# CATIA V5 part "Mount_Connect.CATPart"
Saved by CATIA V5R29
Part number: Mount_Connect
Source: Unknown
Bounding box of the stored display mesh (mm): x -80 to 35, y -25 to 25, z -45 to 45
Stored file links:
  C:\Users\Administrator\Desktop\프로젝트\Boxfold\Guide\Mount_Connect.CATPart
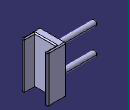
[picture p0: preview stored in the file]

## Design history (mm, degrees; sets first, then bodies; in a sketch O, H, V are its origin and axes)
Body1 (main body)
  Solid1 "PartBody": solid without history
